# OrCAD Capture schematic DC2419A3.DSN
size Custom
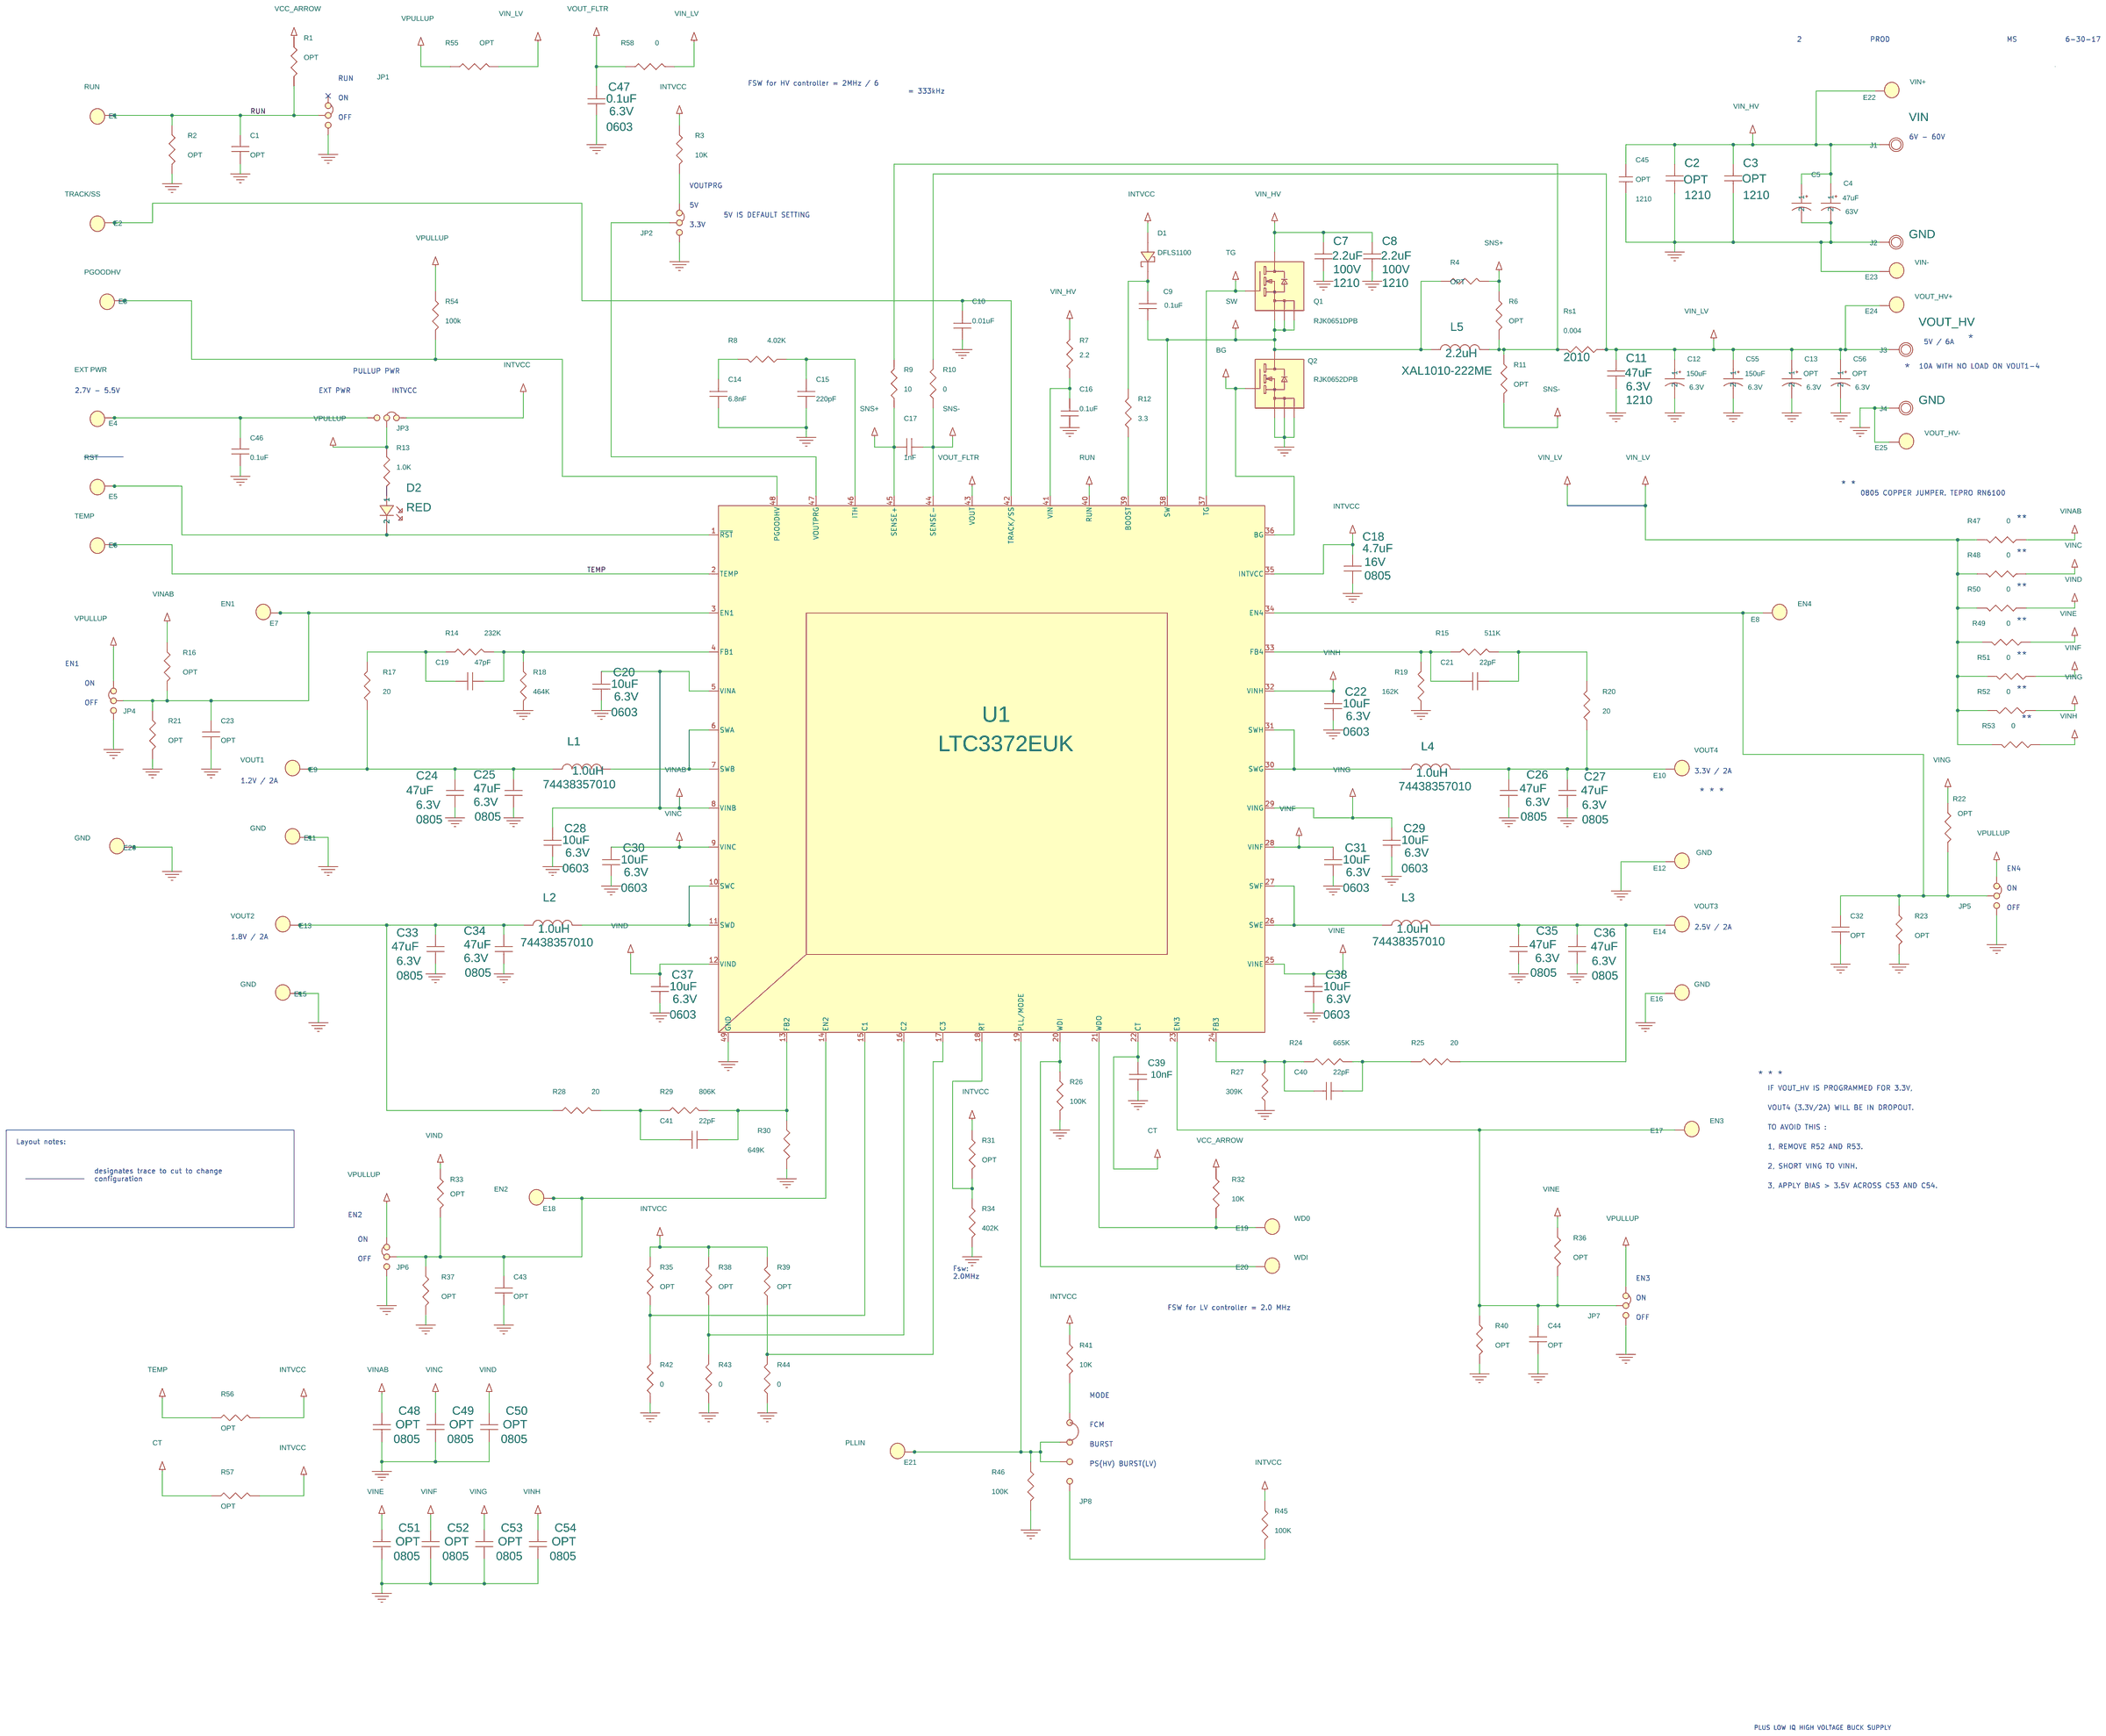
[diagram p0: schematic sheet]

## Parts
C1  OPT  [0603]
C2  OPT  [1210]
C3  OPT  [1210]
C4  47uF  [SANYO_10MMX10MM]
C5  47uF  [SANYO_10MMX10MM]
C7  2.2uF  [1210]
C8  2.2uF  [1210]
C9  0.1uF  [0603]
C10  0.01uF  [0402]
C11  47uF  [1210]
C12  150uF  [B-3528]
C13  OPT  [B-3528]
C14  6.8nF  [0402]
C15  220pF  [0402]
C16  0.1uF  [0603]
C17  1nF  [0402]
C18  4.7uF  [0805]
C19  47pF  [0402]
C20  10uF  [0603]
C21  22pF  [0402]
C22  10uF  [0603]
C23  OPT  [0603]
C24  47uF  [0805]
C25  47uF  [0805]
C26  47uF  [0805]
C27  47uF  [0805]
C28  10uF  [0603]
C29  10uF  [0603]
C30  10uF  [0603]
C31  10uF  [0603]
C32  OPT  [0603]
C33  47uF  [0805]
C34  47uF  [0805]
C35  47uF  [0805]
C36  47uF  [0805]
C37  10uF  [0603]
C38  10uF  [0603]
C39  10nF  [0402]
C40  22pF  [0402]
C41  22pF  [0402]
C43  OPT  [0603]
C44  OPT  [0603]
C45  OPT  [1210]
C46  0.1uF  [0603]
C47  0.1uF  [0603]
C48  OPT  [0805]
C49  OPT  [0805]
C50  OPT  [0805]
C51  OPT  [0805]
C52  OPT  [0805]
C53  OPT  [0805]
C54  OPT  [0805]
C55  150uF  [B-3528]
C56  OPT  [B-3528]
D1  DFLS1100  [POWERDI123_a]
D2  RED  [WURTH_LED(s)]
E1  Testpoint  [MM/2501]
E2  Testpoint  [MM/2501]
E3  Testpoint  [MM/2501]
E4  Testpoint  [MM/2501]
E5  Testpoint  [MM/2501]
E6  Testpoint  [MM/2501]
E7  Testpoint  [MM/2501]
E8  Testpoint  [MM/2501]
E9  Testpoint  [MM/2501]
E10  Testpoint  [MM/2501]
E11  Testpoint  [MM/2501]
E12  Testpoint  [MM/2501]
E13  Testpoint  [MM/2501]
E14  Testpoint  [MM/2501]
E15  Testpoint  [MM/2501]
E16  Testpoint  [MM/2501]
E17  Testpoint  [MM/2501]
E18  Testpoint  [MM/2501]
E19  Testpoint  [MM/2501]
E20  Testpoint  [MM/2501]
E21  Testpoint  [MM/2501]
E22  Testpoint  [MM/2501]
E23  Testpoint  [MM/2501]
E24  Testpoint  [MM/2501]
E25  Testpoint  [MM/2501]
E26  Testpoint  [MM/2501]
J1  VIN  [key-575-4]
J2  GND  [key-575-4]
J3  VOUT_HV  [key-575-4]
J4  GND  [key-575-4]
JP1  JMP1X3  [JUMPER3\2MM]
JP2  JMP1X3  [JUMPER3\2MM]
JP3  JMP1X3  [JUMPER3\2MM]
JP4  JMP1X3  [JUMPER3\2MM]
JP5  JMP1X3  [JUMPER3\2MM]
JP6  JMP1X3  [JUMPER3\2MM]
JP7  JMP1X3  [JUMPER3\2MM]
JP8  JP3X1/079\NO\12  [SIP\4P\2MM]
L1  1.0uH  [XAL4020(30)-5030]
L2  1.0uH  [XAL4020(30)]
L3  1.0uH  [XAL4020(30)]
L4  1.0uH  [XAL4020(30)-5030]
L5  2.2uH  [XAL1010]
Q1  RJK0651DPB  [LFPAK]
Q2  RJK0652DPB  [LFPAK]
R1  OPT  [0603]
R2  OPT  [0603]
R3  10K  [0603]
R4  OPT  [0603]
R6  OPT  [0402]
R7  2.2  [0603]
R8  4.02K  [0402]
R9  10  [0402]
R10  0  [0402]
R11  OPT  [0402]
R12  3.3  [0603]
R13  1.0K  [0603]
R14  232K  [0402]
R15  511K  [0402]
R16  OPT  [0603]
R17  20  [0603]
R18  464K  [0402]
R19  162K  [0402]
R20  20  [0603]
R21  OPT  [0603]
R22  OPT  [0603]
R23  OPT  [0603]
R24  665K  [0402]
R25  20  [0603]
R26  100K  [0603]
R27  309K  [0402]
R28  20  [0603]
R29  806K  [0402]
R30  649K  [0402]
R31  OPT  [0402]
R32  10K  [0603]
R33  OPT  [0603]
R34  402K  [0402]
R35  OPT  [0402]
R36  OPT  [0603]
R37  OPT  [0603]
R38  OPT  [0402]
R39  OPT  [0402]
R40  OPT  [0603]
R41  10K  [0603]
R42  0  [0402]
R43  0  [0402]
R44  0  [0402]
R45  100K  [0603]
R46  100K  [0603]
R47  0  [0805]
R48  0  [0805]
R49  0  [0805]
R50  0  [0805]
R51  0  [0805]
R52  0  [0805]
R53  0  [0805]
R54  100k  [0603]
R55  OPT  [0603]
R56  OPT  [0402]
R57  OPT  [0402]
R58  0  [0603]
Rs1  0.004  [2010]
U1  LTC3372EUK  [UK_48_7MMX7MM]

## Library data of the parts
C1 C17 C19 C21 C23 C32 C40 C41 C43 C44 C46 = 06033A101JAT2A: CAP, 0603 OPT; Part Number: AVX 06033A101JAT2A
C2 C3 = C1608X5R0J475M: 1st Part Field: 100V; 3rd Part Field: CHIP; 4th Part Field: TDK; 5th Part Field: C3225JB2A105K200AA; 7th Part Field: CAP, X5R; Part Number: GRM21BR60J476ME15L; Tolerance: 20%
C4 = tant_2: CAP ALUM POLYMER 47uF 63V 10mm x 10.5mm; Part Number: SUNCON HVH47M; Voltage: 63V
C5 = tant_3: CAP ALUM POLYMER 47uF 63V 10mm x 10.5mm; Part Number: SUNCON HVH47M; Voltage: 63V
C7 C8 = C1608X5R0J475M: 1st Part Field: 100V; 3rd Part Field: CHIP; 4th Part Field: TDK; 5th Part Field: C3225JB2A225M230AB; 7th Part Field: CAP, X5R; Part Number: GRM21BR60J476ME15L; Tolerance: 20%
C9 C10 C16 = CAP_NP_0: VOLTAGE: 50V
C11 C25 C26 C34 C35 = C1608X5R0J475M: 1st Part Field: 6.3V; 3rd Part Field: CHIP; 4th Part Field: TDK; 5th Part Field: GRM155R60J225ME15; 7th Part Field: CAP, X5R; Part Number: GRM21BR60J476ME15L; Tolerance: 20%
C12 = tant_5: CAP, 7343 150uF 20% 6.3V POLYMER TANTALUM; Part Number: KEMET T520D157M006ATE015; Voltage: 6.3V
C13 = tant_4: CAP, 7343 OPT; Part Number: KEMET T520D157M006ATE015; Voltage: 6.3V
C14 C15 = CAP_NP_0: VOLTAGE: ( Opt. )
C18 = C1608X5R0J475M: 1st Part Field: 16V; 3rd Part Field: CHIP; 4th Part Field: MURATA; 5th Part Field: GRM155R60J225ME15; 7th Part Field: CAP, X5R; Part Number: C2012X5R0J336M; Tolerance: 20%
C20 C22 C28-C31 C37 C38 C47 = C1608X5R0J475M: 1st Part Field: 6.3V; 3rd Part Field: CHIP, X5R; 4th Part Field: MUR; 5th Part Field: C1608X5R0J106M; 7th Part Field: CAP, X5R; Tolerance: 20%
C24 C27 C33 C36 C48-C54 = C1608X5R0J475M: 1st Part Field: 6.3V; 3rd Part Field: CHIP; 4th Part Field: TDK; 5th Part Field: GRM155R60J225ME15; 7th Part Field: CAP, X5R; Part Number: C2012X5R0J336M; Tolerance: 20%
C39 = C1608X5R0J475M: 1st Part Field: 6.3V; 2nd Part Field: 0603; 3rd Part Field: CHIP, X5R; 4th Part Field: MUR; 5th Part Field: GRM188R60J106ME47; 7th Part Field: CAP, X5R; Tolerance: 20%
C45 = CAP-NP: CAP, 1210 22uF 10% 16V X5R; Part Number: MURATA GRM32ER61C226KE20L; Voltage rating: 16V
C55 = tant: CAP, 7343 OPT; Part Number: KEMET T520D157M006ATE015; Voltage: 6.3V
C56 = tant_1: CAP, 7343 OPT; Part Number: KEMET T520D157M006ATE015; Voltage: 6.3V
D1 = DIODE_SCHOTTKY31_3
D2 = LNJ208R8ARA_(RED-LED)
E1 = MillMax-2501_1: TURRET; 9th Part Field: RUN; Part Number: MILL MAX 2501-2-00-80-00-00-07-0
E2 = MillMax-2501_1: TURRET; 9th Part Field: TRACK/SS; Part Number: MILL MAX 2501-2-00-80-00-00-07-0
E3 = MillMax-2501_1: TURRET; 9th Part Field: PGOODHV; Part Number: MILL MAX 2501-2-00-80-00-00-07-0
E4 = MillMax-2501_1: TURRET; 9th Part Field: EXT PWR; Part Number: MILL MAX 2501-2-00-80-00-00-07-0
E5 = MillMax-2501_1: TURRET; 9th Part Field: RST; Part Number: MILL MAX 2501-2-00-80-00-00-07-0
E6 = MillMax-2501_1: TURRET; 9th Part Field: TEMP; Part Number: MILL MAX 2501-2-00-80-00-00-07-0
E7 = MillMax-2501_1: TURRET; 9th Part Field: EN1; Part Number: MILL MAX 2501-2-00-80-00-00-07-0
E8 = MillMax-2501_1: TURRET; 9th Part Field: EN4; Part Number: MILL MAX 2501-2-00-80-00-00-07-0
E9 = MillMax-2501_1: TURRET; 9th Part Field: VOUT1; Part Number: MILL MAX 2501-2-00-80-00-00-07-0
E10 = MillMax-2501_1: TURRET; 9th Part Field: VOUT4; Part Number: MILL MAX 2501-2-00-80-00-00-07-0
E11 E12 E15 E16 E26 = MillMax-2501_1: TURRET; 9th Part Field: GND; Part Number: MILL MAX 2501-2-00-80-00-00-07-0
E13 = MillMax-2501_1: TURRET; 9th Part Field: VOUT2; Part Number: MILL MAX 2501-2-00-80-00-00-07-0
E14 = MillMax-2501_1: TURRET; 9th Part Field: VOUT3; Part Number: MILL MAX 2501-2-00-80-00-00-07-0
E17 = MillMax-2501_1: TURRET; 9th Part Field: EN3; Part Number: MILL MAX 2501-2-00-80-00-00-07-0
E18 = MillMax-2501_1: TURRET; 9th Part Field: EN2; Part Number: MILL MAX 2501-2-00-80-00-00-07-0
E19 = MillMax-2501_1: TURRET; 9th Part Field: WD0; Part Number: MILL MAX 2501-2-00-80-00-00-07-0
E20 = MillMax-2501_1: TURRET; 9th Part Field: WDI; Part Number: MILL MAX 2501-2-00-80-00-00-07-0
E21 = MillMax-2501_1: TURRET; 9th Part Field: PLLIN; Part Number: MILL MAX 2501-2-00-80-00-00-07-0
E22 = MillMax-2501_1: TURRET; 9th Part Field: VIN+; Part Number: MILL MAX 2501-2-00-80-00-00-07-0
E23 = MillMax-2501_1: TURRET; 9th Part Field: VIN-; Part Number: MILL MAX 2501-2-00-80-00-00-07-0
E24 = MillMax-2501_1: TURRET; 9th Part Field: VOUT_HV+; Part Number: MILL MAX 2501-2-00-80-00-00-07-0
E25 = MillMax-2501_1: TURRET; 9th Part Field: VOUT_HV-; Part Number: MILL MAX 2501-2-00-80-00-00-07-0
J1-J4 = TP_KEY_1502-2_0: JACK, BANANA; Part Number: KEYSTONE 575-4
JP1 JP2 JP4-JP7 = JMP1X3_0: HEADER,3PIN, 2mm; Part Number: SAMTEC TMM-103-02-L-S
JP3 = JMP1X3_1: HEADER,3PIN, 2mm; Part Number: SAMTEC TMM-103-02-L-S
JP8 = JP3X1_079_NO_12_0
L1-L4 = CR75-100MC: 4th Part Field: CoilCraft; 5th Part Field: 74438357010; Part Number: (OPTIONAL FDSD05XX)
L5 = CR75-100MC: 4th Part Field: CoilCraft; 5th Part Field: XAL1010-222ME; Part Number: (OPTIONAL FDSD05XX)
Q1 Q2 = 2N7002_26
R1 R2 R35 R38 R39 R54 R55 R58 = NRC06F5230TRF: RES, 0603 OPT; Part Number: VISHAY CRCW0603562RFKEA
R3 R16 R22 R33 R36 R56 R57 = NRC06F5230TRF: RES, 0603 10 kOHMS 1% 1/10W; Part Number: VISHAY CRCW0603562RFKEA
R4 R6 R11 R31 R34 = NRC06F5230TRF: RES, 0603 402k OHMS 1% 1/10W; Part Number: VISHAY CRCW0603562RFKEA
R7 R9 R10 R12 Rs1 = R_1: %: 0.1%
R8 R13-R15 R18 R19 R24 R27 R29 R30 R41 R45-R53 = NRC06F5230TRF: RES, 0603 562 OHMS 1% 1/10W; Part Number: VISHAY CRCW0603562RFKEA
R17 R20 R25 R28 R42-R44 = NRC06F5230TRF: RES, 0603 0 Ohms; Part Number: VISHAY CRCW0603562RFKEA
R21 R23 R26 R32 R37 R40 = NRC06F5230TRF: RES, 0603 1 MOhm; Part Number: VISHAY CRCW0603562RFKEA
U1 = LTC1629_23: IC, DUAL OUTPUT BUCK CONTROLLER; Part Number: LINEAR TECH. LTC3860EUH

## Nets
GND: C1.2 C2.2 C3.2 C4.2 C5.2 C7.2 C8.2 C10.1 C11.2 C12.2 C13.2 C14.1 C15.1 C16.1 C18.2 C20.1 C22.1 C23.2 C24.2 C25.2 C26.2 C27.2 C28.1 C29.1 C30.1 C31.1 C32.2 C33.2 C34.2 C35.2 C36.2 C37.1 C38.1 C39.1 C43.2 C44.2 C45.1 C46.2 C47.1 C48.2 C49.2 C50.2 C51.2 C52.2 C53.2 C54.2 C55.2 C56.2 E11.1 E12.1 E15.1 E16.1 E23.1 E25.1 E26.1 J2.1 J4.1 JP1.3 JP2.3 JP4.3 JP5.3 JP6.3 JP7.3 Q2.1 Q2.2 Q2.3 R2.2 R18.2 R19.2 R21.2 R23.2 R26.2 R27.2 R30.2 R34.2 R37.2 R40.2 R42.1 R43.1 R44.1 R46.2 U1.49(GND)
VIN_HV: C2.1 C3.1 C4.1 C5.1 C7.1 C8.1 C45.2 E22.1 J1.1 Q1.5 R1.1 R7.2
VIN_LV: C11.1 C12.1 C13.1 C55.1 C56.1 E24.1 J3.1 R10.2 R47.2 R48.2 R49.2 R50.2 R51.2 R52.2 R53.2 R55.2 R58.2 Rs1.2
VINAB: C20.2 C28.2 C48.1 R16.1 R47.1 U1.5(VINA) U1.8(VINB)
VINC: C30.2 C49.1 R48.1 U1.9(VINC)
VIND: C37.2 C50.1 R33.1 R50.1 U1.12(VIND)
VINE: C38.2 C51.1 R36.1 R49.1 U1.25(VINE)
VINF: C31.2 C52.1 R51.1 U1.28(VINF)
VING: C29.2 C53.1 R22.1 R52.1 U1.29(VING)
VINH: C22.2 C54.1 R53.1 U1.32(VINH)
BG: Q2.4 U1.36(BG)
CT: C39.2 R57.1 U1.22(CT)
INTVCC: C18.1 D1.1(ANODE) JP3.1 R3.1 R31.1 R35.2 R38.2 R39.2 R41.1 R45.1 R56.2 R57.2 U1.35(INTVCC)
RUN: C1.1 E1.1 JP1.2 R1.2 R2.1 U1.40(RUN)
SNS+: C17.2 R4.2 R6.1 R9.1 U1.45(SENSE+)
SNS-: C17.1 R10.1 R11.2 U1.44(SENSE-)
SW: C9.1 L5.1 Q1.1 Q1.2 Q1.3 Q2.5 R4.1 U1.38(SW)
TEMP: E6.1 R56.1 U1.2(TEMP)
TG: Q1.4 U1.37(TG)
VOUT_FLTR: C47.2 R58.1 U1.43(VOUT)
VPULLUP: JP3.2 JP4.1 JP5.1 JP6.1 JP7.1 R13.1 R32.1 R54.1 R55.1
N27574026: C24.1 C25.1 E9.1 L1.1 R17.1
N27575098: L2.2 U1.10(SWC) U1.11(SWD)
N27578758: L3.1 U1.26(SWE) U1.27(SWF)
N27579826: C26.1 C27.1 E10.1 L4.2 R20.1
N27579881: L4.1 U1.30(SWG) U1.31(SWH)
N27651658: D2.2 E5.1 U1.1(~{RST})
N27658128: C33.1 C34.1 E13.1 L2.1 R28.1
N27661889: C35.1 C36.1 E14.1 L3.2 R25.2
N27670679: C23.1 E7.1 JP4.2 R16.2 R21.1 U1.3(EN1)
N27676977: C43.1 E18.1 JP6.2 R33.2 R37.1 U1.14(EN2)
N27678216: C44.1 E17.1 JP7.2 R36.2 R40.1 U1.23(EN3)
N27685720: C19.1 R14.2 R18.1 U1.4(FB1)
N27687315: C19.2 R14.1 R17.2
N27690295: C41.2 R28.2 R29.1
N27690332: C41.1 R29.2 R30.1 U1.13(FB2)
N27701845: C40.1 R24.1 R25.1
N27701881: C40.2 R24.2 R27.1 U1.24(FB3)
N27703739: C21.1 R15.1 R20.2
N27703776: C21.2 R15.2 R19.1 U1.33(FB4)
N27727958: R35.1 R42.2 U1.15(C1)
N27785672: C32.1 E8.1 JP5.2 R22.2 R23.1 U1.34(EN4)
N27788558: JP8.4 R45.2
N27811175: R38.1 R43.2 U1.16(C2)
N27819306: E20.1 R26.1 U1.20(WDI)
N27836197: E19.1 R32.2 U1.21(WDO)
N27847144: R39.1 R44.2 U1.17(C3)
N28042481: C9.2 D1.2(CATHODE) R12.2
N28043567: R12.1 U1.39(BOOST)
N28048339: E3.1 R54.2 U1.48(PGOODHV)
N28071048: C16.2 R7.1 U1.41(VIN)
N28081375: L5.2 R6.2 R9.2 R11.1 Rs1.1
N28096159: JP2.2 U1.47(VOUTPRG)
N28097662: C10.2 E2.1 U1.42(TRACK/SS)
N28140378: C15.2 R8.1 U1.46(ITH)
N28145399: C14.2 R8.2
N28184230: E21.1 JP8.2 JP8.3 R46.1 U1.19(PLL/MODE)
N28287230: R31.2 R34.1 U1.18(RT)
N28734850: JP8.1 R41.2
N28756801: JP2.1 R3.2
N28830109: C46.1 E4.1 JP3.3
N28835699: D2.1 R13.2
N28902860: L1.2 U1.6(SWA) U1.7(SWB)

Not connected (* = marked no-connect by the designer): JP1 1*

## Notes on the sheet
- 2
- PROD
- MS
- 6-30-17
- RUN
- FSW for HV controller = 2MHz / 6
                                             = 333kHz
- ON
- OFF
- 6V - 60V
- VOUTPRG
- 5V
- 5V IS DEFAULT SETTING
- 3.3V
- *
- 5V / 6A
- PULLUP PWR
- *
- 10A WITH NO LOAD ON VOUT1-4
- 2.7V - 5.5V
- EXT PWR
- INTVCC
- *
- *
- 0805 COPPER JUMPER. TEPRO RN6100
- **
- **
- **
- **
- **
- EN1
- ON
- **
- OFF
- **
- 3.3V / 2A
- 1.2V / 2A
- *
- *
- *
- EN4
- ON
- OFF
- 2.5V / 2A
- 1.8V / 2A
- *
- *
- *
- IF VOUT_HV IS PROGRAMMED FOR 3.3V,
- VOUT4 (3.3V/2A) WILL BE IN DROPOUT.
- TO AVOID THIS :
- Layout notes:
- 1, REMOVE R52 AND R53.
- 2, SHORT VING TO VINH.
- designates trace to cut to change
  configuration
- 3, APPLY BIAS > 3.5V ACROSS C53 AND C54.
- EN2
- ON
- OFF
- Fsw:
  2.0MHz
- EN3
- ON
- FSW for LV controller = 2.0 MHz
- OFF
- MODE
- FCM
- BURST
- PS(HV) BURST(LV)
- PLUS LOW IQ HIGH VOLTAGE BUCK SUPPLY
